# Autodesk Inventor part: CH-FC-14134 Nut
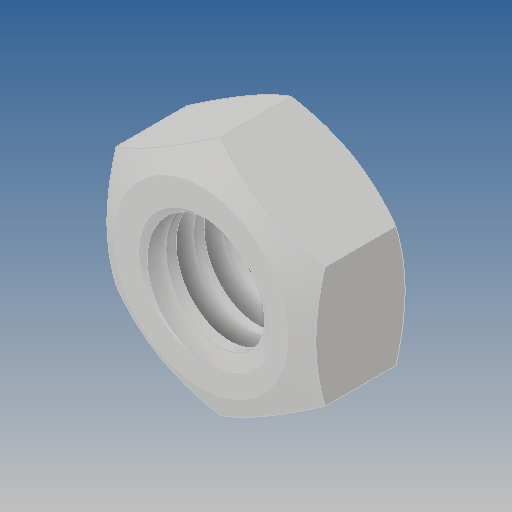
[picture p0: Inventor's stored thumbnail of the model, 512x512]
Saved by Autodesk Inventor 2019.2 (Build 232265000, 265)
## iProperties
Created: 2015-08
Part Number: CH-FC-14134 Nut
Material: Ogólny
Document SubType Name: Modeling
Designer: CADENGINEERING4
Density: 1 g/cm^3
Appearance: Domyślna
Author: CADENGINEERING4
Revision Number: ÈÎºÎ
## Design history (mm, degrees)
feature "ÇÐ³ý-É¨Ãè1"
node "Bryła1"
